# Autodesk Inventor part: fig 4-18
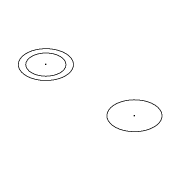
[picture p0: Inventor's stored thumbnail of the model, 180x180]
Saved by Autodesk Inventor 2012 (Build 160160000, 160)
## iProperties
Created: 2005-02
Part Number: fig 4-18
Document SubType Name: Modeling
Designer: CADCIM
Manufacturer: Standard
Standards Organization: Custom
Density: 1 g/cm^3
Material: Default
Author: CADCIM
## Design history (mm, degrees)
sketch "Sketch1"
  geometry: C1 r 7.935 at (-23.563, 7.599); C2 r 7.935 at (12.452, 7.599); C3 r 5.782 at (-23.563, 7.599)
  constraints: 3 centre point, 1 coincident, 1 equal radius, 1 other
